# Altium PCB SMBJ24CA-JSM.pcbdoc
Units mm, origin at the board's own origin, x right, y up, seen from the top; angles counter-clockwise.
Board outline 19.28 x 16.47 mm, 2 copper layers (Top Layer, Bottom Layer), stack 0 mm thick; 1 components, 0 nets, 2 pads, 0 vias.
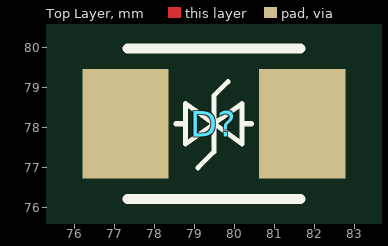
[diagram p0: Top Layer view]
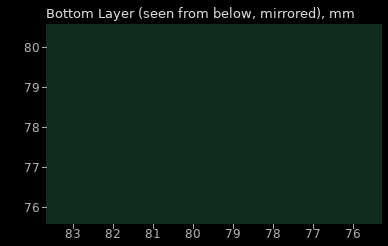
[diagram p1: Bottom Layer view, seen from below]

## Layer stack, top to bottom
Top Layer: signal copper (thickness not stored)
Bottom Layer: signal copper (thickness not stored)

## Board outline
89.129,69.85 69.85,69.85 69.85,86.323 89.129,86.323

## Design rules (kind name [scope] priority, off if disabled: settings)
PasteMaskExpansion "Paste Mask Expansion" [All] p1: expansion=0
SolderMaskExpansion "Solder Mask Expansion" [IsVia] p1: expansion=-25.4 istentingtop=TRUE
SolderMaskExpansion "Solder Mask Expansion" [All] p2: expansion=0.051 istentingtop=FALSE

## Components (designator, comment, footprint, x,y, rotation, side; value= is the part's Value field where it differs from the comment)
D? "SMBJ24CA-JSM" SMB_L4.5-W3.7-LS5.4-BI 79.489,78.095 r0 top

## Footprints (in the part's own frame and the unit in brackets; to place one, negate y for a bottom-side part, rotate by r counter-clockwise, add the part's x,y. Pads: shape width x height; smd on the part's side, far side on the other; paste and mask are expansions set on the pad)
SMB_L4.5-W3.7-LS5.4-BI [mil]
  rect 85x108 smd: 1(-87,0) 2(87,0)
  silkscreen extent -85,-74 85,74

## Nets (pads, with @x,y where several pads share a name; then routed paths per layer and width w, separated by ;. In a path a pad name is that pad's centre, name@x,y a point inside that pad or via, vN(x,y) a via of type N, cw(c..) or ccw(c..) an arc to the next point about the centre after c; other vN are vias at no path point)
pads on no net: D?.1 D?.2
